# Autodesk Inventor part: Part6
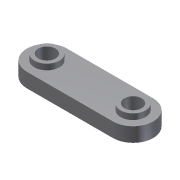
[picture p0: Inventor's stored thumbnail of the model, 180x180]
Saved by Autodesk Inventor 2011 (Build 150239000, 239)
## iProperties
Shininess: 77.0
Length Units: 11269
Angle Units: 11279
Time Units: 11290
Mass Units: 11283
Length Display Precision: 3
Angle Display Precision: 2
Created: 2002-01
Part Number: Part6
Document SubType Name: Modeling
Designer: ***
Density: 1 g/cm^3
Mass: 21.6911 g
Surface Area: 77.1136 cm^2
Volume: 21.6911 cm^3
Density: 0.0
Volumn: 0.0
Area: 0.0
PropertySet Name: Model Information
Control State: 0
Master: False
Checked Out: False
Author: ***
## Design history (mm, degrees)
sketch "Sketch1"
  geometry: L1 (-33.118, 12.346)-(26.882, 12.361); L2 (-33.111, -15.654)-(26.889, -15.639); C1 r 6 at (-33.114, -1.654); C2 r 6 at (26.886, -1.639); A1 r 14 centre (-33.114, -1.654) between (-33.118, 12.346) and (-33.111, -15.654); A2 r 14 centre (26.886, -1.639) between (26.889, -15.639) and (26.882, 12.361)
  constraints: 4 centre point, 4 end point, 4 point on circle, 4 tangent, 2 coincident, 2 equal radius
  dimensions: "d0" = 60 distance of L1.start L1.end; "d1" = 14 radius of A1; "d2" = 12 diameter of C1
extrude "Extrusion1" new body sketch "Sketch1" distance "d3" = 10; taper "d4" = 0 deg
sketch "Sketch2"
  geometry: C1 r 6 at (26.886, -1.639) reference; C2 r 6 at (-33.114, -1.654) reference; C3 r 8.694 at (-33.114, -1.654); C4 r 8.694 at (26.886, -1.639)
  constraints: 2 centre point, 2 coincident, 1 equal radius
extrude "Extrusion2" join sketch "Sketch2" distance "d5" = 4; taper "d6" = 0 deg
body "Solid1"
